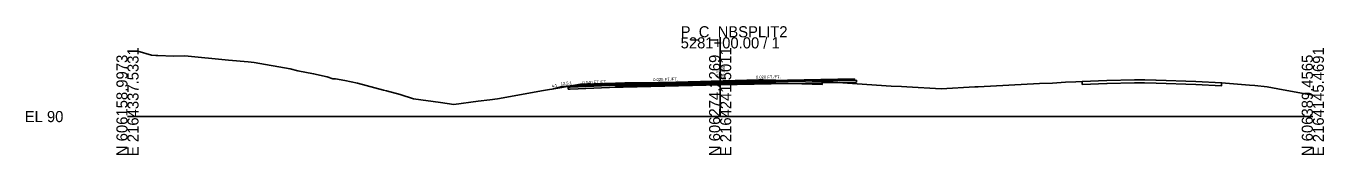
# Model space of a CAD drawing. Extents: x -26 to 1303, y -10 to 12038.
# Drawn here: x -25.7 to 302.8, y 990.3 to 1022.8 of the extents above; entities that cross this region are included whole.
import ezdxf

# ---------------------------------------------------------------- set-up
doc = ezdxf.new("R2010")
doc.units = 0
for name, color, linetype in [('RD_GPK_XS_Cell', 7, 'Continuous'), ('RD_XS_Base', 7, 'Continuous'), ('RD_XS_ExGround', 7, 'Continuous'), ('RD_XS_ExPaveRet', 7, 'Continuous'), ('RD_XS_Greenside', 7, 'Continuous'), ('RD_XS_Pave', 7, 'Continuous'), ('RD_XS_PaveOvlay_CP', 7, 'Continuous'), ('RD_XS_TieSlope', 7, 'Continuous'), ('RD_XS_TX_Elev_EX', 7, 'Continuous'), ('RD_XS_TX_Elev_PR', 7, 'Continuous'), ('RD_XS_TX_ShdSlope', 7, 'Continuous'), ('RD_XS_TX_Slope', 7, 'Continuous')]:
    doc.layers.add(name, color=color, linetype=linetype)

msp = doc.modelspace()

# ---------------------------------------------------------------- linework, layer by layer
at = {"layer": 'RD_GPK_XS_Cell'}
for p, q in [((150, 1000), (150, 1020)), ((0, 1000), (150, 1000)), ((150, 1000), (300, 1000))]:
    msp.add_line(p, q, dxfattribs=at)
at = {"layer": 'RD_XS_Base'}
for p, q in [((150, 1008.52), (184, 1009.2)), ((184.5, 1008.71), (150, 1008.02)), ((150, 1008.02), (150, 1008.68)), ((150, 1008.68), (150, 1008.68)), ((150, 1008.68), (150, 1008.68)), ((150, 1008.68), (150, 1008.52)), ((174, 1009), (174, 1009)), ((174, 1009), (174, 1009)), ((184, 1009.2), (184, 1009.2)), ((184.5, 1009.21), (184.5, 1008.71)), ((184.5, 1009.18), (184.5, 1009.18)), ((112, 1007.42), (111.5, 1007.4)), ((111.5, 1007.4), (111.5, 1007.4)), ((111.5, 1007.4), (111.5, 1006.9)), ((111.5, 1006.9), (112, 1006.92)), ((122, 1007.82), (112, 1007.42)), ((112, 1007.42), (112, 1007.42)), ((112, 1006.92), (122, 1007.32)), ((112, 1006.92), (112, 1006.92)), ((150, 1008.52), (122, 1007.82)), ((122, 1007.32), (150, 1008.02)), ((122, 1007.82), (122, 1007.82)), ((122, 1007.32), (122, 1007.32)), ((150, 1008.52), (150, 1008.52)), ((150, 1008.02), (150, 1008.52)), ((150, 1008.52), (150, 1008.52)), ((150, 1008.52), (150, 1008.52)), ((150, 1008.02), (150, 1008.02)), ((174, 1008.5), (174, 1008.5)), ((174, 1008.5), (174, 1008.5))]:
    msp.add_line(p, q, dxfattribs=at)
at = {"layer": 'RD_XS_ExGround'}
msp.add_lwpolyline([(0, 1016.45), (2.26, 1016.49), (2.46, 1016.49), (2.61, 1016.47), (6.09, 1015.49), (7.19, 1015.43), (7.65, 1015.37), (11.64, 1015.26), (14.49, 1015.3), (25.6, 1014.26), (30.52, 1013.85), (32.04, 1013.62), (41.2, 1012.02), (43.11, 1011.5), (47.12, 1010.79), (50.55, 1010.01), (51.97, 1009.5), (52.67, 1009.48), (54.99, 1009.13), (58.18, 1008.44), (64.78, 1006.65), (65.55, 1006.48), (69.05, 1005.57), (72.39, 1004.47), (79.26, 1003.52), (82.61, 1003.04), (88.78, 1003.86), (91.73, 1004.24), (93.69, 1004.5), (96.02, 1004.93), (104.76, 1006.49), (109.44, 1007.28), (114.64, 1008.17), (118, 1008.29), (123.55, 1008.45), (125.9, 1008.48), (134.28, 1008.59), (138.77, 1008.71), (145, 1008.88), (147.7, 1008.95), (159.8, 1009.27), (160.06, 1009.27), (160.85, 1009.27), (167.3, 1009.09), (170.68, 1009), (175.79, 1008.83), (178.63, 1008.68), (182.21, 1008.42), (193.3, 1007.71), (195.88, 1007.58), (197.25, 1007.48), (205.92, 1007.03), (214.46, 1007.46), (215.28, 1007.5), (230.82, 1008.3), (234.13, 1008.46), (237.43, 1008.66), (239.98, 1008.79), (241.66, 1008.88), (247.88, 1009.06), (254.86, 1009.24), (257.17, 1009.29), (257.36, 1009.28), (257.38, 1009.27), (257.43, 1009.28), (260.32, 1009.17), (270.4, 1008.84), (276.91, 1008.54), (283.99, 1007.89), (285.33, 1007.8), (288.42, 1007.49), (291.14, 1007.02), (298.08, 1005.74), (299.05, 1005.55), (300, 1005.42)], dxfattribs=at)
at = {"layer": 'RD_XS_ExPaveRet'}
for points in [[(170.68, 1009), (167.3, 1009.09), (160.85, 1009.27), (160.85, 1009.27), (160.85, 1009.27), (160.85, 1009.27), (160.06, 1009.27), (159.8, 1009.27), (159.8, 1009.27), (159.8, 1009.27), (147.7, 1008.95), (147.7, 1008.95), (145, 1008.88), (138.77, 1008.71), (138.77, 1008.71), (134.28, 1008.59), (134.28, 1008.59), (125.9, 1008.48), (125.9, 1008.48), (123.55, 1008.45), (123.55, 1008.45), (123.55, 1008.45), (123.55, 1007.7), (123.55, 1007.7), (125.9, 1007.73), (125.9, 1007.73), (134.28, 1007.84), (134.28, 1007.84), (138.77, 1007.96), (138.77, 1007.96), (145, 1008.13), (147.7, 1008.2), (147.7, 1008.2), (159.8, 1008.52), (159.8, 1008.52), (159.8, 1008.52), (160.06, 1008.52), (160.85, 1008.52), (160.85, 1008.52), (160.85, 1008.52), (160.85, 1008.52), (167.3, 1008.34), (170.68, 1008.25), (170.68, 1008.25), (175.78, 1008.08), (175.78, 1008.83), (175.78, 1008.83), (170.68, 1009), (170.68, 1009)], [(170.68, 1009), (167.3, 1009.09), (160.85, 1009.27), (160.06, 1009.27), (159.8, 1009.27), (147.7, 1008.95), (145, 1008.88), (138.77, 1008.71), (134.28, 1008.59), (125.9, 1008.48), (123.55, 1008.45), (123.55, 1007.7), (125.9, 1007.73), (134.28, 1007.84), (138.77, 1007.96), (145, 1008.13), (147.7, 1008.2), (159.8, 1008.52), (160.06, 1008.52), (160.85, 1008.52), (167.3, 1008.34), (170.68, 1008.25), (175.78, 1008.08), (175.78, 1008.83), (170.68, 1009)], [(270.4, 1008.84), (260.32, 1009.17), (260.32, 1009.17), (257.43, 1009.28), (257.43, 1009.28), (257.38, 1009.27), (257.36, 1009.28), (257.17, 1009.29), (257.17, 1009.29), (257.17, 1009.29), (257.17, 1009.29), (254.86, 1009.24), (254.86, 1009.24), (247.88, 1009.06), (247.88, 1009.06), (247.88, 1009.06), (241.66, 1008.88), (241.66, 1008.88), (241.66, 1008.13), (247.88, 1008.31), (247.88, 1008.31), (247.88, 1008.31), (254.86, 1008.49), (254.86, 1008.49), (257.17, 1008.54), (257.17, 1008.54), (257.17, 1008.54), (257.17, 1008.54), (257.36, 1008.53), (257.38, 1008.52), (257.43, 1008.53), (257.43, 1008.53), (260.32, 1008.42), (260.32, 1008.42), (270.4, 1008.09), (270.4, 1008.09), (276.91, 1007.79), (276.91, 1008.54), (276.91, 1008.54), (270.4, 1008.84), (270.4, 1008.84)], [(270.4, 1008.84), (260.32, 1009.17), (257.43, 1009.28), (257.38, 1009.27), (257.36, 1009.28), (257.17, 1009.29), (254.86, 1009.24), (247.88, 1009.06), (241.66, 1008.88), (241.66, 1008.13), (247.88, 1008.31), (254.86, 1008.49), (257.17, 1008.54), (257.36, 1008.53), (257.38, 1008.52), (257.43, 1008.53), (260.32, 1008.42), (270.4, 1008.09), (276.91, 1007.79), (276.91, 1008.54), (270.4, 1008.84)]]:
    msp.add_lwpolyline(points, dxfattribs=at)
at = {"layer": 'RD_XS_Greenside'}
msp.add_line((110, 1007.58), (107.51, 1006.95), dxfattribs=at)
at = {"layer": 'RD_XS_Pave'}
for p, q in [((150, 1008.84), (122, 1008.14)), ((150, 1008.68), (122, 1007.98)), ((122, 1007.98), (150, 1008.68)), ((184, 1009.52), (150, 1008.84)), ((184, 1009.36), (150, 1008.68)), ((150, 1008.68), (184, 1009.36)), ((150, 1008.52), (184.5, 1009.21)), ((150, 1008.84), (150, 1008.84)), ((150, 1008.52), (150, 1008.68)), ((150, 1008.68), (150, 1008.68)), ((150, 1008.68), (150, 1008.68)), ((150, 1008.68), (150, 1008.68)), ((150, 1008.68), (150, 1008.68)), ((150, 1008.68), (150, 1008.52)), ((150, 1008.68), (150, 1008.68)), ((174, 1009.32), (174, 1009.32)), ((174, 1009.32), (174, 1009.32)), ((174, 1009.16), (174, 1009.16)), ((174, 1009.16), (174, 1009.16)), ((174, 1009.16), (174, 1009.16)), ((174, 1009.16), (174, 1009.16)), ((174, 1009), (174, 1009)), ((174, 1009), (174, 1009)), ((184, 1009.36), (184, 1009.52)), ((184, 1009.52), (184, 1009.52)), ((184, 1009.2), (184, 1009.36)), ((184, 1009.36), (184, 1009.36)), ((122, 1008.14), (112, 1007.74)), ((122, 1007.98), (112, 1007.58)), ((112, 1007.58), (122, 1007.98)), ((112, 1007.42), (122, 1007.82)), ((112, 1007.74), (112, 1007.74)), ((112, 1007.74), (112, 1007.58)), ((112, 1007.58), (112, 1007.58)), ((112, 1007.58), (112, 1007.42)), ((122, 1007.82), (150, 1008.52)), ((122, 1008.14), (122, 1008.14)), ((122, 1007.98), (122, 1007.98)), ((122, 1007.98), (122, 1007.98)), ((122, 1007.82), (122, 1007.82)), ((150, 1008.52), (150, 1008.52)), ((150, 1008.52), (150, 1008.52))]:
    msp.add_line(p, q, dxfattribs=at)
at = {"layer": 'RD_XS_PaveOvlay_CP'}
for p, q in [((150, 1008.84), (122, 1008.14)), ((184, 1009.52), (150, 1008.84)), ((150, 1008.84), (150, 1008.84)), ((174, 1009.32), (174, 1009.32)), ((174, 1009.32), (174, 1009.32)), ((122, 1008.14), (112, 1007.74)), ((122, 1008.14), (122, 1008.14))]:
    msp.add_line(p, q, dxfattribs=at)
at = {"layer": 'RD_XS_TieSlope'}
msp.add_line((112, 1007.74), (110, 1007.58), dxfattribs=at)

# ---------------------------------------------------------------- texts
at = {"layer": 'RD_GPK_XS_Cell'}
for s, p in [('P_C_NBSPLIT2', (140, 1020)), ('5281+00.00 / 1', (140, 1017.2)), ('EL 90', (-26, 998.6))]:
    msp.add_text(s, height=2.8, dxfattribs=at).set_placement(p)
for s, p in [('N 606158.9973', (0, 990)), ('E 2164337.5331', (2.8, 990)), ('N 606274.2269', (150, 990)), ('E 2164241.5011', (152.8, 990)), ('N 606389.4565', (300, 990)), ('E 2164145.4691', (302.8, 990))]:
    msp.add_text(s, height=2.8, rotation=90, dxfattribs=at).set_placement(p)
at = {"layer": 'RD_XS_TX_Elev_EX'}
msp.add_text('99.01', height=0.6, rotation=90, dxfattribs=at).set_placement((149.65, 1009.84))
at = {"layer": 'RD_XS_TX_Elev_PR'}
msp.add_text('98.84', height=1, rotation=90, dxfattribs=at).set_placement((151.25, 1009.31))
at = {"layer": 'RD_XS_TX_ShdSlope'}
msp.add_text('12.5:1', height=0.75, rotation=4.5739, dxfattribs=at).set_placement((109.66, 1007.9))
at = {"layer": 'RD_XS_TX_Slope'}
for s, rotation, p in [('0.040 FT./FT.', 2.2906, (115.14, 1008.16)), ('0.025 FT./FT.', 1.4321, (133.06, 1008.93)), ('0.020 FT./FT.', 1.1458, (159.06, 1009.54)), ('4:1', 14.0362, (107.44, 1007.24))]:
    msp.add_text(s, height=0.75, rotation=rotation, dxfattribs=at).set_placement(p)

doc.saveas('drawing.dxf')
